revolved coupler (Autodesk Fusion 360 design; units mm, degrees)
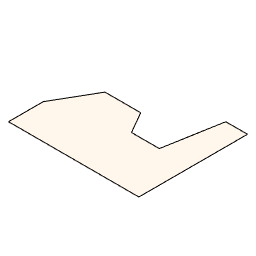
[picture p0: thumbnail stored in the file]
sketch "Sketch1" plane through (0, 0, 0) normal (0, 1, 0) x axis (1, 0, 0)
  line L1 (-50, 75) -> (-50, -50)
  line L2 (-75, 75) -> (-50, 75)
  line L3 (-86.4613, 10) -> (-75, 75)
  line L4 (-118.4613, 10) -> (-86.4613, 10)
  line L5 (-132.895, 35) -> (-118.4613, 10)
  line L6 (-174.0192, 35) -> (-132.895, 35)
  line L7 (-200, -10) -> (-174.0192, 35)
  line L8 (-200, -50) -> (-200, -10)
  line L9 (-50, -50) -> (-200, -50)
  point P1 (0, 0)
  point P2 (-50, -50)
  point P3 (-50, 75)
  point P4 (-75, 75)
  point P5 (-86.4613, 10)
  point P6 (-118.4613, 10)
  point P10 (-200, -50)
  point P9 (-200, -10)
  vertical L1
  perpendicular L1 L2
  parallel L2 L6
  perpendicular L6 L8
  horizontal L9
  horizontal L4
  dimension "d1" distance P1 L1 = 50
  dimension "d2" distance P2 P3 = 125
  dimension "d3" distance P3 P4 = 25
  dimension "d4" angle L2 L3 = 100
  dimension "d5" angle L5 L6 = 120
  dimension "d6" distance L4 L9 = 60
  dimension "d7" distance P5 P6 = 32
  dimension "d8" distance L6 L9 = 85
  dimension "d9" angle L6 L7 = 120
  dimension "d10" distance P2 P10 = 150
  dimension "d11" distance P9 P10 = 40
  dimension "d12" distance P1 L9 = 50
